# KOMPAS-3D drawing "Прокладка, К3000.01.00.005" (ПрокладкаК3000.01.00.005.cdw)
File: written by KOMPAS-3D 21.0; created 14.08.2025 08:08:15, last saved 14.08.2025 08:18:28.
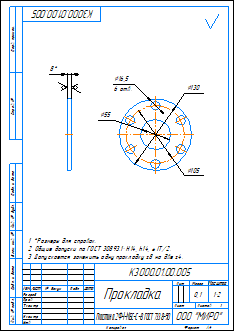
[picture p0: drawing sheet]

Sheet 1: A4, portrait

Document properties: Автор: admin; Полное имя файла: C:\Users\ShavarinML\Desktop\Стапель\2D\ПрокладкаК3000.01.00.005.cdw; Масса: 0.098452

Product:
- Part/product: Прокладка  | designation К3000.01.00.005
    Материал: Рукав 6-18-120-У ГОСТ 25452-2017 (density 1280 kg/m3)
    Масса: 0.098452

Title block, sheet 1: Наименование: Прокладка; designation: К3000.01.00.005; Материал: Пластина 2Ф-І-МБС-С-8 ГОСТ 7338-90; Масса: 0,1; Количество листов документа: 1; organisation: ООО "МИРО"; Форматы листов документа: A4

Views: Спереди 1, Спереди, Проекционный вид 2
Referenced files in C:\Users\ShavarinML\Desktop\Стапель\Из трубы\: Прокладка.m3d
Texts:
  К3000.01.00.005 Прокладка
Dimensions and other numbers on the sheet: 8; 130; 105; 55; 16,5; 6 отв.; 1:2; 1; 0,1

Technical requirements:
  *Размеры для справок.
  Общие допуски по ГОСТ 30893.1: H14, h14,   IT/2.
  Допускается заменить одну прокладку s8 на две s4.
